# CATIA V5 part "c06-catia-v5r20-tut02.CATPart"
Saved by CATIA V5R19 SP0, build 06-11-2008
Part number: Part1
Bounding box of the stored display mesh (mm): x -75 to 75, y -125 to 125, z -14 to 14
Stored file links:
  D:\Shriniwas\v5_r19\Part files\c06\c06_tut2.CATPart
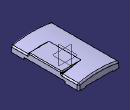
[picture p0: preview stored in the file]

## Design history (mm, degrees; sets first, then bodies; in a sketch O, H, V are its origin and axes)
Body1 (main body)
  Sketch1 on zx-plane, origin (0, 0, 0), H (-1, 0, 0), V (0, 0, 1)
    construction line L1 (75, 14) -> (75, -14)
    line L2 (75, -14) -> (-75, -14)
    construction line L3 (-75, -14) -> (-75, 14)
    construction line L4 (-75, 14) -> (75, 14)
    point P3 (-75, -14)
    arc A1 centre (0, -336) radius 350 from (-75, 5.8699) to (75, 5.8699) cw
    point P5 (0, -336)
    point P6 (-75, 5.8699)
    point P7 (75, 5.8699)
    line L5 (-75, -14) -> (-75, 5.8699)
    point P8 (-75, -14)
    line L6 (75, -14) -> (75, 5.8699)
    length L2 = 150
    radius A1 = 350
    length L3 = 28
    vertical: L1 V, L3 V, L5 V, L6 V
    horizontal: L2 H, L4 H
    equidistance: L1 L3 O, L2 L4 O
    coincidence: P6 L3, P7 L1, P8 L3, P5 V, P8 P3
    tangency: A1 L4
  Pad1: profile Sketch1, direction (0, 1, 0), length 125, mirrored extent
  Plane1: type Offset, Offset 28, RefPlane face of Pad1 from Sketch1.L2
  Sketch2 on Plane1, origin (0, 0, 14), H (1, 0, 0), V (0, 1, 0)
    line L1 (75, -62.5) -> (0, -62.5)
    line L2 (0, -62.5) -> (0, 62.5)
    line L3 (0, 62.5) -> (75, 62.5)
    line L4 (75, 62.5) -> (75, -62.5)
    reference projected line E1 (75, -125) -> (75, 125) from edge [face of Pad1 from Sketch1.L5 | face of Pad1 from Sketch1.A1]
    length L4 = 125
    distance L3 H = 62.5
    length L1 = 75
    horizontal: L1 H, L3 H
    vertical: L2 V, L4 V
    coincidence: E1 L4
  Pad2: profile Sketch2, direction (0, 0, -1), up to the existing solid (limit type 2)
  Draft1: Angle 3, SupportToDraft (end face of Pad1; face of Pad2; face of Pad1 from Sketch1.L6; start face of Pad1; face of Pad2 from Sketch2.L1; face of Pad2 from Sketch2.L3), PullDir face of Pad1 from Sketch1.L2, Neutral face of Pad1 from Sketch1.L2
  Fillet1: radius 3, on edge [face of Pad2 | start face of Pad2]; edge [face of Pad2 from Sketch2.L1 | start face of Pad2]; edge [face of Pad2 from Sketch2.L3 | start face of Pad2]
  Fillet2: radius 1, on edge [face of Pad2 from Sketch2.L1 | face of Pad1 from Sketch1.A1]; edge [face of Pad2 from Sketch2.L3 | face of Pad1 from Sketch1.A1]
  Fillet3: radius 5, on edge [face of Pad2 | face of Pad1 from Sketch1.A1] (x2); edge [end face of Pad1 | face of Pad1 from Sketch1.A1]; edge [face of Pad1 from Sketch1.L6 | face of Pad1 from Sketch1.A1]; edge [start face of Pad1 | face of Pad1 from Sketch1.A1]; edge [face of Pad2 | end face of Pad1]; edge [face of Pad1 from Sketch1.L6 | end face of Pad1]; edge [start face of Pad1 | face of Pad2]; edge [start face of Pad1 | face of Pad1 from Sketch1.L6]
  Shell1: ExtOffset 0, IntOffset 2, Face face of Pad1 from Sketch1.L2
  Sketch3 on yz-plane, origin (0, 0, 0), H (0, 1, 0), V (0, 0, 1)
    line L1 (75, -14) -> (-75, -14)
    line L2 (-75, -14) -> (-75, -7)
    line L3 (-75, -7) -> (75, -7)
    line L4 (75, -7) -> (75, -14)
    reference projected line E1 (125, -14) -> (-125, -14) from edge [face of Pad2 | face of Pad1 from Sketch1.L2]
    length L1 = 150
    length L2 = 7
    distance L2 V = 75
    horizontal: L1 H, L3 H
    vertical: L2 V, L4 V
    coincidence: L1 E1
  Pocket1: profile Sketch3, direction (-1, 0, 0), through (limit type 3), opposite side length 125
  Sketch4 on zx-plane, origin (0, 0, 0), H (-1, 0, 0), V (0, 0, 1)
    line L1 (50, -14) -> (-50, -14)
    line L2 (-50, -14) -> (-50, -11)
    line L3 (-50, -11) -> (50, -11)
    line L4 (50, -11) -> (50, -14)
    reference projected line E1 (75, -14) -> (-75, -14) from edge [end face of Pad1 | face of Pad1 from Sketch1.L2]
    length L1 = 100
    length L2 = 3
    distance L2 V = 50
    horizontal: L1 H, L3 H
    vertical: L2 V, L4 V
    coincidence: L1 E1
  Pocket2: profile Sketch4, direction (0, -1, 0), through (limit type 3), opposite side length 125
